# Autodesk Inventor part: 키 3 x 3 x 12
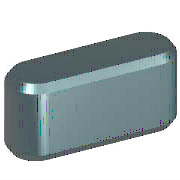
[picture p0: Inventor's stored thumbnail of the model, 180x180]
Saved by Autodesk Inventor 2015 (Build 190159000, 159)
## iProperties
Created: 2012-02
Part Number: 키 3 x 3 x 12
Material: 강철, 연강
Description: 키 및 해당 키홈
Document SubType Name: Modeling
Standard: KS B 1311
Designer: mduedu
Standards Organization: KS
Language: ko-KR
Size Designation: 3 x 3 x 12
Categories: <MemberInstance><Categories><Category DisplayName="샤프트 부품" InternalName="7f7aeb1f-a693-4053-b835-cee3144e0d98" Mnemonic="SHFT"><Category DisplayName="키" Interna
Density: 7.85 g/cm^3
Appearance: 노란색
Mass: 0.789117 g
Surface Area: 1.42216 cm^2
Volume: 0.100524 cm^3
IsCustomPart: 1
Author: mduedu
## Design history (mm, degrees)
workplane "Work Plane1"
workplane "Work Plane2"
sketch "스케치1"
  geometry: L1 (1.5, 1.5)-(10.5, 1.5); L2 (10.5, -1.5)-(1.5, -1.5); L3 (0, 9.4)-(0, -7.4) reference; L4 (-5, 0)-(30, 0) reference; L5 (12, 0)-(12, 7); A1 r 1.5 centre (1.5, 0) between (1.5, 1.5) and (1.5, -1.5); A2 r 1.5 centre (10.5, 0) between (10.5, -1.5) and (10.5, 1.5)
  constraints: 6 end point, 5 point on circle, 4 tangent, 3 point on line, 2 centre point, 1 horizontal, 1 parallel, 1 perpendicular
  dimensions: "d0" = 1.5 radius of A1 (= 0.5 x PB); "d13" = 1.5 radius of A2 (= 0.5 x PB); "d14" = 12 distance between parallel lines of L5 L3 (= NLG)
extrude "본체1" new body sketch "스케치1" taper "d3" = 0 deg; stored distance "d4" = 10
workplane "Work Plane3"
body "Solid1"
chamfer "모따기1" distance "d8" = 0.25 (= PHH); stored, may be unused: second distance "d9" = 0.25 (= PHH), angle "d15" = 45 deg
other parameters: "d1" = -1.8 (= -PNT), "d2" = 1.2 (= PH - PNT), "NLG" = 12 [user parameter; used in 3 equation terms], "PB" = 3 [user parameter; used in 2 equation terms], "PNT" = 1.8 [user parameter; used in 2 equation terms], "PH" = 3 [user parameter; used in 1 equation term], "PHH" = 0.25 [user parameter; used in 2 equation terms], "d10" = 0, "d16" = 0, "d17" = 0, "d18" = 0, "WDMIN" = 8 [user parameter], "PLB2" = 12 (= NLG) [user parameter], "PLB1" = 12 (= NLG) [user parameter], "RR" = 0.08 [user parameter], "PUEB" = 1.4 [user parameter]
